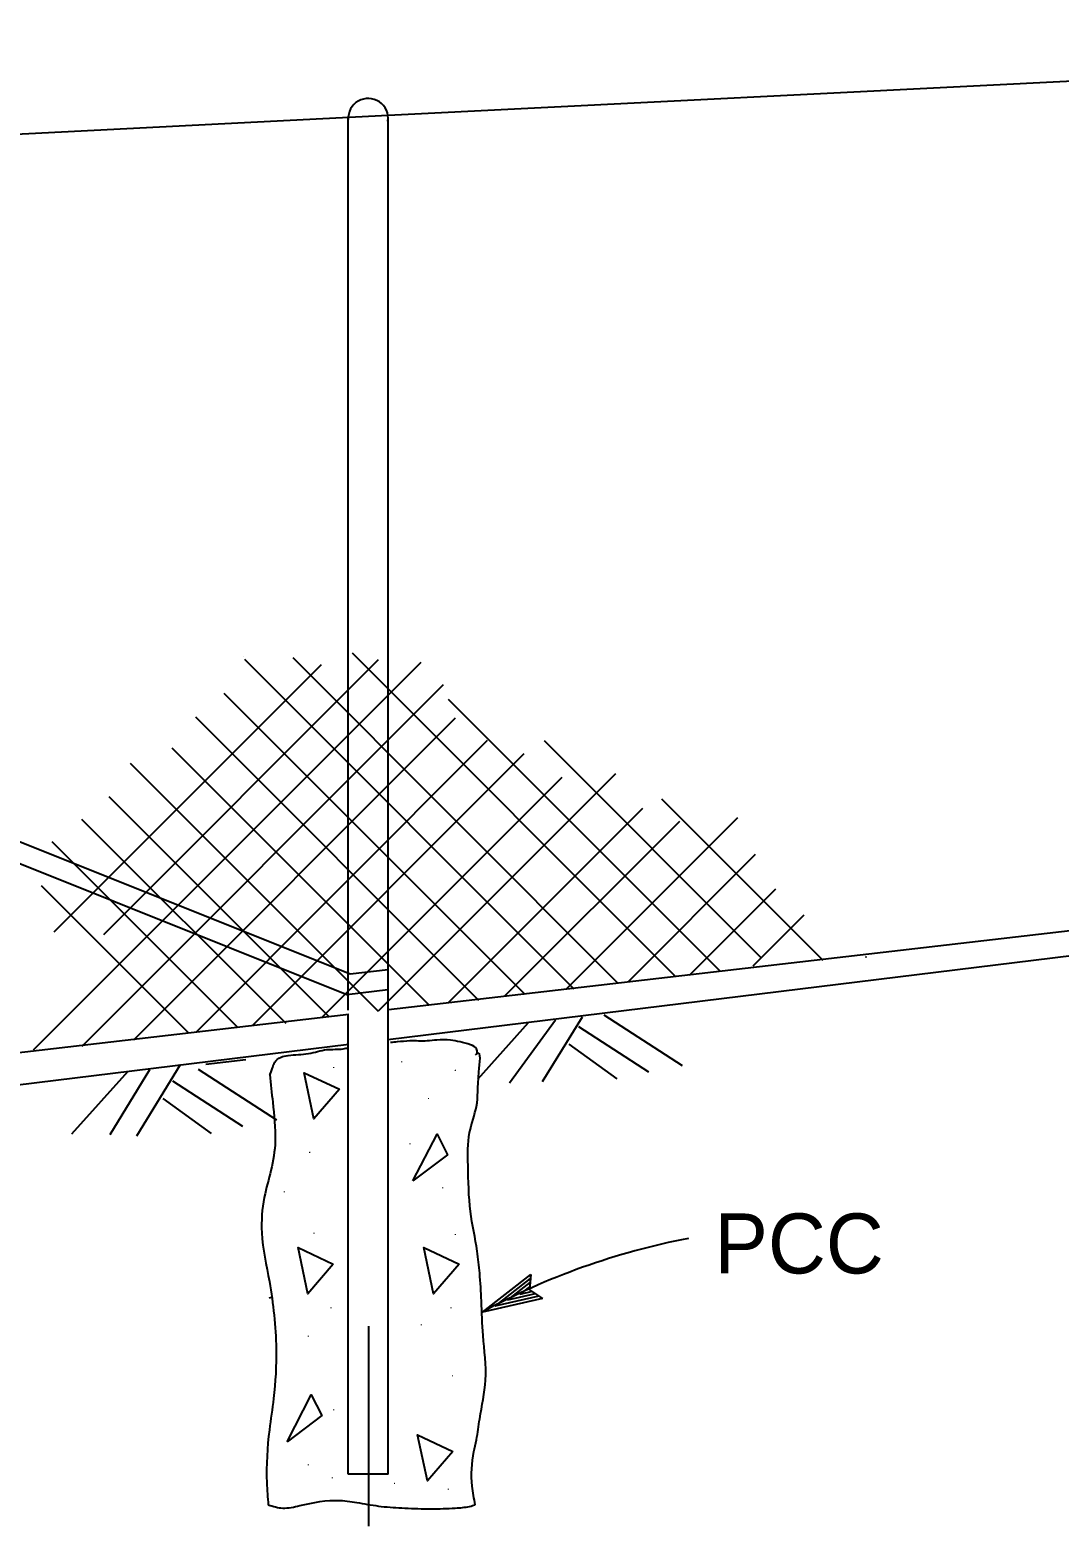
# Model space of a CAD drawing. Extents: x 6710407 to 6714861, y 1868090 to 1871317.
# Drawn here: x 6711838.5 to 6711941.5, y 1870323 to 1870472.6 of the extents above; entities that cross this region are included whole.
import ezdxf

# ---------------------------------------------------------------- set-up
doc = ezdxf.new("R2010")
doc.units = 0
for name, color, linetype in [('G-MARK', 7, 'Continuous'), ('G-TEXT', 7, 'Continuous'), ('Nongeo Data(60)', 7, 'Continuous')]:
    doc.layers.add(name, color=color, linetype=linetype)

msp = doc.modelspace()

# ---------------------------------------------------------------- linework, layer by layer
at = {"layer": 'G-MARK'}
msp.add_lwpolyline([(6711872.38, 1870342.97), (6711872.36, 1870322.97)], dxfattribs=at)
msp.add_arc((6711917.78, 1870281.68), 71.32, 100.834, 118.4731, dxfattribs=at)
at = {"layer": 'G-TEXT'}
for p, q in [((6711883.78, 1870344.37), (6711888.63, 1870348.14)), ((6711885.03, 1870344.97), (6711888.57, 1870347.71)), ((6711888.63, 1870348.14), (6711888.48, 1870346.59)), ((6711888.63, 1870348.14), (6711888.63, 1870348.14)), ((6711886.27, 1870345.55), (6711888.56, 1870347.32)), ((6711889.06, 1870346.18), (6711886.27, 1870345.55)), ((6711887.52, 1870346.14), (6711888.5, 1870346.9)), ((6711888.75, 1870346.42), (6711887.52, 1870346.14)), ((6711888.48, 1870346.59), (6711889.77, 1870345.72)), ((6711889.77, 1870345.72), (6711883.78, 1870344.37)), ((6711889.43, 1870345.95), (6711885.02, 1870344.96)), ((6711889.77, 1870345.72), (6711889.77, 1870345.72)), ((6711883.78, 1870344.37), (6711883.78, 1870344.37))]:
    msp.add_line(p, q, dxfattribs=at)
at = {"layer": 'Nongeo Data(60)'}
for p, q in [((6711874.34, 1870464.05), (6712043.57, 1870472.58)), ((6711834, 1870462.01), (6711874.34, 1870464.05)), ((6711870.34, 1870374.57), (6711870.34, 1870463.73)), ((6711874.34, 1870374.54), (6711874.34, 1870463.73)), ((6711710.34, 1870442.2), (6711870.54, 1870378.19)), ((6711710.39, 1870440.02), (6711870.22, 1870376.14)), ((6711877.61, 1870409.34), (6711838.84, 1870370.57)), ((6711867.64, 1870409.1), (6711840.9, 1870382.36)), ((6711873.34, 1870409.58), (6711845.86, 1870382.1)), ((6711859.89, 1870409.9), (6711859.89, 1870409.9)), ((6711859.97, 1870409.65), (6711892.93, 1870376.69)), ((6711864.79, 1870409.81), (6711897.33, 1870377.27)), ((6711870.73, 1870410.29), (6711903.09, 1870377.93)), ((6711879.86, 1870407.08), (6711843.7, 1870370.92)), ((6711857.91, 1870406.25), (6711888, 1870376.17)), ((6711880.34, 1870405.66), (6711907.55, 1870378.45)), ((6711881.05, 1870403.76), (6711848.86, 1870371.57)), ((6711855.06, 1870403.88), (6711883.38, 1870375.56)), ((6711884.25, 1870401.51), (6711855.12, 1870372.37)), ((6711889.95, 1870401.51), (6711911.67, 1870379.79)), ((6711852.69, 1870400.8), (6711878.37, 1870375.12)), ((6711887.93, 1870400.2), (6711860.76, 1870373.03)), ((6711848.54, 1870399.25), (6711873.34, 1870374.45)), ((6711891.73, 1870397.83), (6711867.68, 1870373.78)), ((6711897.07, 1870398.18), (6711873.34, 1870374.45)), ((6711846.4, 1870395.93), (6711868.4, 1870373.93)), ((6711901.7, 1870395.69), (6711917.84, 1870379.55)), ((6711899.8, 1870394.74), (6711880.37, 1870375.32)), ((6711843.67, 1870393.67), (6711864.09, 1870373.25)), ((6711874.36, 1870374.61), (6712039.44, 1870393.81)), ((6711903.48, 1870393.44), (6711885.96, 1870375.91)), ((6711909.29, 1870393.79), (6711892.12, 1870376.62)), ((6711840.7, 1870391.42), (6711859.27, 1870372.85)), ((6711874.31, 1870371.63), (6712039.3, 1870391.89)), ((6711911.07, 1870390.11), (6711898.35, 1870377.39)), ((6711839.64, 1870387.03), (6711854.38, 1870372.28)), ((6711913.09, 1870386.67), (6711904.44, 1870378.02)), ((6711915.94, 1870384.06), (6711910.82, 1870378.95)), ((6711922.08, 1870379.9), (6711922.19, 1870379.9)), ((6711870.54, 1870378.19), (6711874.34, 1870378.63)), ((6711870.22, 1870376.14), (6711874.32, 1870376.62)), ((6711874.34, 1870328.17), (6711874.34, 1870374.5)), ((6711707.34, 1870355.18), (6711870.41, 1870374.15)), ((6711870.34, 1870328.17), (6711870.34, 1870374.1)), ((6711888.36, 1870373.3), (6711883.27, 1870367.61)), ((6711891.09, 1870373.57), (6711886.48, 1870367.25)), ((6711893.74, 1870373.87), (6711889.75, 1870367.4)), ((6711895.92, 1870374.1), (6711903.76, 1870369.02)), ((6711893.38, 1870372.93), (6711900.38, 1870368.39)), ((6711705.48, 1870350.9), (6711870.41, 1870371.15)), ((6711892.4, 1870371.16), (6711897.22, 1870367.68)), ((6711850.48, 1870368.58), (6711846.49, 1870362.1)), ((6711853.54, 1870369.08), (6711849.15, 1870361.95)), ((6711855.32, 1870368.66), (6711863.16, 1870363.58)), ((6711856.11, 1870369.16), (6711860.1, 1870369.62)), ((6711848.29, 1870368.44), (6711842.67, 1870362.16)), ((6711852.78, 1870367.49), (6711859.78, 1870362.95)), ((6711851.8, 1870365.71), (6711856.62, 1870362.23)), ((6711874.34, 1870328.17), (6711870.34, 1870328.17))]:
    msp.add_line(p, q, dxfattribs=at)
for points in [[(6711869.47, 1870366.66), (6711866.92, 1870363.7), (6711865.94, 1870368.3)], [(6711876.82, 1870357.48), (6711879.23, 1870362.16), (6711880.28, 1870360.1)], [(6711868.85, 1870349.16), (6711866.31, 1870346.2), (6711865.33, 1870350.81)], [(6711881.43, 1870349.16), (6711878.88, 1870346.2), (6711877.91, 1870350.81)], [(6711864.25, 1870331.39), (6711866.65, 1870336.08), (6711867.71, 1870334.02)], [(6711880.82, 1870330.44), (6711878.27, 1870327.49), (6711877.29, 1870332.09)]]:
    msp.add_lwpolyline(points, close=True, dxfattribs=at)
msp.add_lwpolyline([(6711862.66, 1870345.83), (6711862.43, 1870345.77)], dxfattribs=at)
msp.add_arc((6711872.34, 1870463.73), 2, 352.4216, 183.1965, dxfattribs=at)
for points in [[(6711883.25, 1870370.24), (6711883.17, 1870370.7), (6711882.59, 1870371.09), (6711881.53, 1870371.38), (6711880.57, 1870371.57), (6711879.21, 1870371.57), (6711878.25, 1870371.48), (6711876.51, 1870371.48), (6711875.25, 1870371.38), (6711874.59, 1870371.32)], [(6711862.52, 1870368.11), (6711862.8, 1870368.87), (6711862.99, 1870369.35), (6711863.57, 1870369.84), (6711864.34, 1870370.03), (6711866.37, 1870370.22), (6711868.2, 1870370.61), (6711869.85, 1870370.7), (6711870.33, 1870370.8)], [(6711883.05, 1870325.09), (6711882.75, 1870326.96), (6711882.91, 1870330.41), (6711883.17, 1870331.59), (6711883.5, 1870333.7), (6711884.09, 1870337.57), (6711883.84, 1870342.03), (6711883.67, 1870345.48), (6711883.5, 1870348.26), (6711883.25, 1870350.45), (6711882.58, 1870354.41), (6711882.33, 1870359.04), (6711882.49, 1870362.32), (6711883.17, 1870364.93), (6711883.42, 1870368.39), (6711883.25, 1870370.24), (6711883.05, 1870370.09)], [(6711862.52, 1870368.11), (6711862.79, 1870365.35), (6711863.04, 1870361.48), (6711862.62, 1870358.53), (6711861.95, 1870355.84), (6711861.7, 1870352.3), (6711862.46, 1870347.42), (6711863.13, 1870340.69), (6711862.88, 1870335.72), (6711862.46, 1870332.6), (6711862.2, 1870327.3), (6711862.35, 1870325.09)], [(6711862.35, 1870325.09), (6711863.8, 1870324.77), (6711865.49, 1870325.02), (6711869.53, 1870325.53), (6711871.46, 1870325.28), (6711873.65, 1870324.94), (6711876.01, 1870324.77), (6711878.62, 1870324.69), (6711881.06, 1870324.77), (6711882.49, 1870324.94), (6711883.05, 1870325.09)]]:
    msp.add_spline(points, degree=3, dxfattribs=at)

# ---------------------------------------------------------------- texts
for p in [(6711868.83, 1870368.97), (6711875.62, 1870369.54), (6711880.99, 1870368.69), (6711878.31, 1870365.86), (6711876.47, 1870361.33), (6711866.43, 1870360.49), (6711879.72, 1870356.95), (6711863.88, 1870356.53), (6711866.85, 1870352.42), (6711880.99, 1870352.28), (6711868.55, 1870344.93), (6711880.57, 1870344.93), (6711877.6, 1870343.23), (6711866.29, 1870342.1), (6711880.71, 1870338.14), (6711868.83, 1870334.74), (6711866.29, 1870329.23), (6711868.69, 1870327.95), (6711874.91, 1870327.39), (6711880.29, 1870326.82)]:
    msp.add_text('.', height=0.8, rotation=271.1553, dxfattribs=at).set_placement(p)
for s, height, p in [('PCC', 6, (6711906.98, 1870348.23)), ('.', 0.36, (6711862.15, 1870348.64)), ('.', 0.36, (6711862.83, 1870344.57))]:
    msp.add_text(s, height=height, dxfattribs=at).set_placement(p)

doc.saveas('drawing.dxf')
